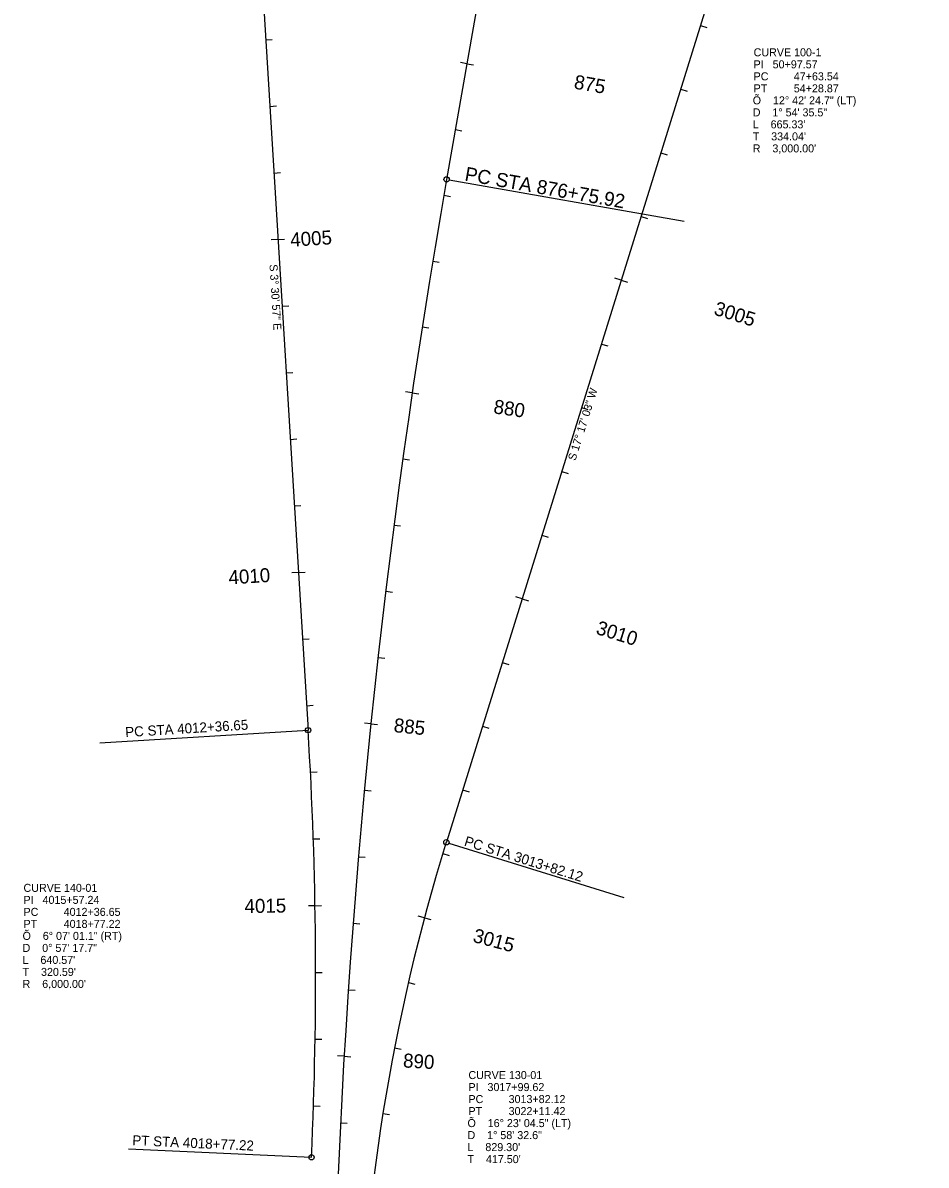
# Model space of a CAD drawing. Extents: x 2819977 to 2827606, y 113942 to 150283.
# Drawn here: x 2820372 to 2821726, y 130332 to 132044 of the extents above; entities that cross this region are included whole.
import ezdxf

# ---------------------------------------------------------------- set-up
doc = ezdxf.new("R2010")
doc.units = 0
for name, color, linetype in [('Level 63', 7, 'Continuous'), ('Roadway-Safety', 7, 'Continuous'), ('Roadway-Signs', 7, 'Continuous'), ('Roadway-Walls', 7, 'Continuous'), ('Utility-Power', 7, 'Continuous')]:
    doc.layers.add(name, color=color, linetype=linetype)

msp = doc.modelspace()

# ---------------------------------------------------------------- linework, layer by layer
at = {"layer": 'Level 63'}
for centre in [(2821007.1, 131809.7), (2820799.5, 130984.2), (2821006.7, 130816.2), (2820804.6, 130344)]:
    msp.add_circle(centre, 4, dxfattribs=at)
at = {"layer": 'Roadway-Safety'}
for p, q in [((2821011, 131809), (2821362.9, 131747.2)), ((2820487.4, 130965.1), (2820799.5, 130984.2)), ((2821010.5, 130815), (2821272.9, 130733.4)), ((2820530.1, 130356.5), (2820804.6, 130344))]:
    msp.add_line(p, q, dxfattribs=at)
at = {"layer": 'Utility-Power'}
for p, q in [((2821447.5, 134317.2), (2821007.1, 131809.7)), ((2820723.6, 132218.6), (2820799.5, 130984.2)), ((2821417.3, 132135.9), (2821006.7, 130816.2)), ((2821387.6, 132040.5), (2821397.2, 132037.5)), ((2820735.9, 132019), (2820745.9, 132019.6)), ((2821037.5, 131982.9), (2821027.7, 131984.7)), ((2821037.5, 131982.9), (2821047.4, 131981.2)), ((2821357.9, 131945), (2821367.5, 131942)), ((2820742, 131919.1), (2820752, 131919.8)), ((2821020.2, 131884.5), (2821030.1, 131882.7)), ((2821328.2, 131849.5), (2821337.8, 131846.5)), ((2820748.2, 131819.3), (2820758.1, 131819.9)), ((2821002.9, 131786), (2821012.8, 131784.2)), ((2821298.5, 131754), (2821308, 131751)), ((2820754.3, 131719.5), (2820744.3, 131718.9)), ((2820754.3, 131719.5), (2820764.3, 131720.1)), ((2820986.3, 131687.4), (2820996.1, 131685.7)), ((2821268.8, 131658.5), (2821259.2, 131661.5)), ((2821268.8, 131658.5), (2821278.3, 131655.5)), ((2820760.4, 131619.7), (2820770.4, 131620.3)), ((2820970.5, 131588.6), (2820980.3, 131587.1)), ((2821239.1, 131563), (2821248.6, 131560.1)), ((2820766.6, 131519.9), (2820776.5, 131520.5)), ((2820955.5, 131489.7), (2820945.6, 131491.2)), ((2820955.5, 131489.7), (2820965.4, 131488.3)), ((2821209.4, 131467.6), (2821218.9, 131464.6)), ((2820772.7, 131420.1), (2820782.7, 131420.7)), ((2820941.4, 131390.7), (2820951.3, 131389.4)), ((2821179.7, 131372.1), (2821189.2, 131369.1)), ((2820778.8, 131320.3), (2820788.8, 131320.9)), ((2820928.2, 131291.6), (2820938.1, 131290.3)), ((2821149.9, 131276.6), (2821159.5, 131273.6)), ((2820785, 131220.5), (2820775, 131219.8)), ((2820785, 131220.5), (2820794.9, 131221.1)), ((2820915.8, 131192.4), (2820925.8, 131191.2)), ((2821120.2, 131181.1), (2821110.7, 131184.1)), ((2821120.2, 131181.1), (2821129.8, 131178.1)), ((2820791.1, 131120.6), (2820801.1, 131121.3)), ((2820904.3, 131093), (2820914.3, 131091.9)), ((2821090.5, 131085.6), (2821100.1, 131082.6)), ((2820797.2, 131020.8), (2820807.2, 131021.4)), ((2820893.7, 130993.6), (2820883.8, 130994.6)), ((2820893.7, 130993.6), (2820903.7, 130992.6)), ((2821060.8, 130990.1), (2821070.4, 130987.2)), ((2820803, 130921), (2820813, 130921.5)), ((2820883.9, 130894.1), (2820893.9, 130893.2)), ((2821031.1, 130894.6), (2821040.7, 130891.7)), ((2820807.3, 130821.1), (2820817.3, 130821.4)), ((2821001.4, 130799.1), (2821011, 130796.2)), ((2820875, 130794.5), (2820885, 130793.6)), ((2820809.8, 130721.1), (2820799.9, 130721)), ((2820809.8, 130721.1), (2820819.8, 130721.3)), ((2820867, 130694.8), (2820877, 130694)), ((2820974, 130703), (2820964.3, 130705.6)), ((2820974, 130703), (2820983.6, 130700.4)), ((2820810.8, 130621.1), (2820820.8, 130621.1)), ((2820859.8, 130595.1), (2820869.8, 130594.4)), ((2820949.8, 130606), (2820959.6, 130603.7)), ((2820810, 130521.1), (2820820, 130521)), ((2820929.1, 130508.1), (2820938.9, 130506.2)), ((2820853.5, 130495.3), (2820843.5, 130495.9)), ((2820853.5, 130495.3), (2820863.5, 130494.7)), ((2820807.6, 130421.2), (2820817.6, 130420.8)), ((2820911.7, 130409.7), (2820921.5, 130408.1)), ((2820848.1, 130395.4), (2820858.1, 130394.9))]:
    msp.add_line(p, q, dxfattribs=at)
for centre, radius, start, end in [((2832333.7, 129820.2), 11500, 170.03806, 202.7163), ((2814810.8, 130616.3), 6000, 357.39887, 3.51583), ((2823775.7, 129954.6), 2900, 162.7159, 179.1005)]:
    msp.add_arc(centre, radius, start, end, dxfattribs=at)

# ---------------------------------------------------------------- texts
at = {"layer": 'Roadway-Safety'}
for s, height, rotation, p in [('PC STA 876+75.92', 21, 350.0381, (2821033.2, 131808.1)), ('PC STA 4012+36.65', 15, 3.5158, (2820525.9, 130973.7)), ('PC STA 3013+82.12', 15, 342.7159, (2821032.4, 130811.4)), ('PT STA 4018+77.22', 15, 357.3989, (2820535.8, 130362.1))]:
    msp.add_text(s, height=height, rotation=rotation, dxfattribs=at).set_placement(p)
at = {"layer": 'Roadway-Signs'}
for s, rotation, p in [('S 3%%d 30\' 57" E', 273.5158, (2820741.6, 131682.1)), ('S 17%%d 17\' 03" W', 72.7159, (2821200.1, 131387.3))]:
    msp.add_text(s, height=12, rotation=rotation, dxfattribs=at).set_placement(p)
at = {"layer": 'Roadway-Walls'}
for s, p in [('CURVE 100-1', (2821467.2, 131994.2)), ('PI   50+97.57', (2821467.2, 131976.2)), ('PC', (2821467.2, 131958.2)), ('47+63.54', (2821527.4, 131958.2)), ('PT', (2821467.2, 131940.2)), ('54+28.87', (2821527.4, 131940.2)), ('Õ    12%%d 42\' 24.7" (LT)', (2821465.9, 131922.2)), ('D    1%%d 54\' 35.5"', (2821465.9, 131904.2)), ("L    665.33'", (2821465.9, 131886.2)), ("T    334.04'", (2821465.9, 131868.2)), ("R    3,000.00'", (2821465.9, 131850.2)), ('CURVE 140-01', (2820373, 130741.8)), ('PI   4015+57.24', (2820373, 130723.8)), ('PC', (2820373, 130705.8)), ('4012+36.65', (2820433.2, 130705.8)), ('PT', (2820373, 130687.8)), ('4018+77.22', (2820433.2, 130687.8)), ('Õ    6%%d 07\' 01.1" (RT)', (2820371.6, 130669.8)), ('D    0%%d 57\' 17.7"', (2820371.6, 130651.8)), ("L    640.57'", (2820371.6, 130633.8)), ("T    320.59'", (2820371.6, 130615.8)), ("R    6,000.00'", (2820371.6, 130597.8)), ('CURVE 130-01', (2821039.8, 130461.2)), ('PI   3017+99.62', (2821039.8, 130443.2)), ('PC', (2821039.8, 130425.2)), ('3013+82.12', (2821100, 130425.2)), ('Õ    16%%d 23\' 04.5" (LT)', (2821038.4, 130389.2)), ('PT', (2821039.8, 130407.2)), ('3022+11.42', (2821100, 130407.2)), ('D    1%%d 58\' 32.6"', (2821038.4, 130371.2)), ("L    829.30'", (2821038.4, 130353.2)), ("T    417.50'", (2821038.4, 130335.2))]:
    msp.add_text(s, height=12, dxfattribs=at).set_placement(p)
at = {"layer": 'Utility-Power'}
for s, rotation, p in [(' 875', 350.0381, (2821189.3, 131947.4)), (' 4005', 3.5158, (2820765.6, 131708.3)), (' 3005', 342.7159, (2821398.9, 131609.7)), (' 880', 351.6527, (2821068.7, 131460.4)), (' 4010', 3.5158, (2820673.1, 131202.1)), (' 3010', 342.7159, (2821222.2, 131131.1)), (' 885', 354.1438, (2820919.4, 130982.2)), (' 4015', 1.0011, (2820696.6, 130709.7)), (' 3015', 345.0448, (2821037.6, 130669.1)), (' 890', 356.635, (2820933.6, 130479.2))]:
    msp.add_text(s, height=21, rotation=rotation, dxfattribs=at).set_placement(p)

doc.saveas('drawing.dxf')
